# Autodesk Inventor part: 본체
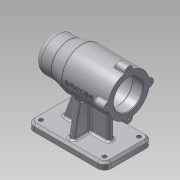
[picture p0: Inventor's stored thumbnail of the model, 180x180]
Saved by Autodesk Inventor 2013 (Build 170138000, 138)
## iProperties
Created: 2019-07
Part Number: 본체
Material: 알루미늄 6061
Document SubType Name: Modeling
Designer: Administrator
Density: 2.71 g/cm^3
Mass: 646.774 g
Surface Area: 654.083 cm^2
Volume: 238.662 cm^3
Author: Administrator
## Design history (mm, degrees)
sketch "스케치1"
  geometry: L1 (0, 0)-(-112, 0); L2 (-112, 0)-(-112, 25); L3 (-112, 25)-(-87, 25); L4 (-87, 25)-(-67, 30); L5 (-67, 30)-(0, 30); L6 (0, 30)-(0, 21); L7 (0, 21)-(-15, 21); L8 (-15, 21)-(-15, 24); L9 (-15, 24)-(-69, 24); L10 (-69, 24)-(-69, 21); L11 (-69, 21)-(-81, 21); L12 (-81, 21)-(-81, 17.5); L13 (-81, 17.5)-(-99, 17.5); L14 (-99, 17.5)-(-99, 16); L15 (-99, 16)-(-103, 16); L16 (-103, 16)-(-103, 10.5); L17 (-103, 10.5)-(-106, 10.5); L18 (-106, 10.5)-(-106, 0); L19 (-112, 0)-(-106, 0); 1 further point
  constraints: 38 end point, 10 horizontal, 8 vertical, 1 midpoint, 1 point on line, 1 vertical alignment
  dimensions: "d0" = 112 distance of L1.start L1.end; "d1" = 21 diameter of L17 L1; "d2" = 32 diameter of L15 L1; "d3" = 35 diameter of L13 L1; "d4" = 42 diameter of L11 L1; "d5" = 42 diameter of L7 L1; "d6" = 48 diameter of L9 L1; "d7" = 50 diameter of L3 L1; "d8" = 60 diameter of L5 L1; "d9" = 25 distance of L2.end L3.end; "d10" = 45 horizontal distance of L2.end L4.end; "d11" = 15 distance of L6.end L7.end; "d12" = 54 distance of L8.end L9.end; "d13" = 12 distance of L10.end L11.end; "d14" = 18 distance of L12.end L13.end; "d15" = 4 distance of L14.end L15.end; "d16" = 3 distance of L16.end L17.end
revolve "회전1" sketch "스케치1" stored, may be unused: angle "d17" = 90 deg
sketch "스케치2"
  geometry: L1 (0, 0)-(0, 30); C1 r 30 at (0, 0) reference; C2 r 6 at (0, 30); 1 further point
  constraints: 2 coincident, 2 end point, 1 centre point, 1 vertical
  dimensions: "d18" = 30 distance of L1.start L1.end; "d19" = 12 diameter of C2
extrude "돌출1" join sketch "스케치2" distance "d20" = 16; taper "d21" = 0 deg
hole "구멍1" sketch "스케치2" diameter "d22" = 3.242; stored, may be unused: countersink angle "d26" = 90 deg, drill point angle "d28" = 118 deg; dims "d23" = 8, "d24" = 4, "d25" = 2, "d27" = 11
fillet "모깎기2" dims "d30" = 3
fillet "모깎기3" dims "d31" = 1
chamfer "모따기1" distance "d35" = 1; stored, may be unused: second distance "d36" = 2, angle "d37" = 45 deg
sketch "스케치3"
  geometry: L1 (-112, -70)-(0, -70); L2 (0, -70)-(0, -80); L3 (0, -80)-(-112, -80); L4 (-112, -80)-(-112, -70); 2 further points
  constraints: 8 end point, 2 parallel, 1 horizontal, 1 midpoint, 1 perpendicular, 1 vertical alignment
  dimensions: "d38" = 80 distance from line of L3 point (0, 0); "d39" = 10 distance of L1.end L2.end; "d40" = 112 distance of L1.start L1.end
extrude "돌출2" join sketch "스케치3" stored distance "d41" = 70; taper "d42" = 0 deg
fillet "모깎기4" dims "d43" = 10
sketch "스케치4"
  geometry: L1 (-10, -10)-(-10, -60) reference; L2 (102, -60)-(102, -10) reference; L3 (10, -31)-(77, -31); L4 (77, -31)-(77, -39); L5 (77, -39)-(10, -39); L6 (10, -39)-(10, -31); 3 further points
  constraints: 8 end point, 2 midpoint, 2 parallel, 1 horizontal, 1 horizontal alignment, 1 perpendicular
  dimensions: "d44" = 8 distance of L3.end L4.end; "d47" = 25 distance between parallel lines of L2 L4; "d48" = 20 distance between parallel lines of L1 L6
extrude "돌출3" join sketch "스케치4" stored distance "d49" = 70; taper "d50" = 0 deg
feature "면 기울기1" dims angle "d51" = 20 deg
node "작업 평면1"
sketch "스케치5"
  geometry: L1 (-80, 35)-(-70, 35) reference; L2 (-70, 28)-(-36.792, 22.144); L3 (-70, -25)-(-70, 25) reference; L4 (-70, 35)-(-70, 25) reference; 1 further point
  constraints: 2 end point, 1 point on line
  dimensions: "d54" = 7 distance of L2.start L1.end; "d56" = 100 deg angle of L2 L3
feature "리브1" sketch "스케치5" dims "d57" = 1, "d58" = 8, "d59" = 0, "d60" = 0, "d61" = 1, "d62" = 1
sketch "스케치6"
  geometry: A1 r 10 centre (92, 10) between (92, 0) and (102, 10) reference; A2 r 10 centre (92, 60) between (102, 60) and (92, 70) reference; A3 r 10 centre (0, 60) between (0, 70) and (-10, 60) reference; A4 r 10 centre (0, 10) between (-10, 10) and (0, 0) reference; 5 further points
  constraints: 4 coincident
hole "구멍2" sketch "스케치6" at (0, 60), (0, 10), (92, 10), (92, 60) diameter "d66" = 6; stored, may be unused: countersink angle "d70" = 90 deg, drill point angle "d72" = 118 deg; dims "d67" = 6, "d68" = 4, "d69" = 2, "d71" = 8
fillet "모깎기13" dims "d78" = 3
fillet "모깎기14" dims "d79" = 3
fillet "모깎기15" dims "d80" = 3, "d81" = 0.3
node "작업 평면2"
sketch "스케치7"
  geometry: 2 further points
  constraints: 1 horizontal alignment, 1 other
  dimensions: "d83" = 42 distance of point (0, 0) point (-42, 0)
feature "엠보싱1" sketch "스케치7" dims "d0" = 112, "d1" = 21, "d2" = 32, "d3" = 35, "d4" = 42, "d5" = 42, "d6" = 48, "d7" = 50, "d8" = 60, "d9" = 25, "d10" = 45, "d11" = 15, "d12" = 54, "d13" = 12, "d14" = 18, "d15" = 4, "d16" = 3, "d84" = 0.5, "d85" = 0
chamfer "모따기2" distance "d86" = 3; stored, may be unused: second distance "d87" = 2, angle "d88" = 45 deg
node "솔리드1"
pattern_circular "원형 패턴1" dims "d33" = 360 deg
mirror "대칭1"
other parameters: "d52" = -56
